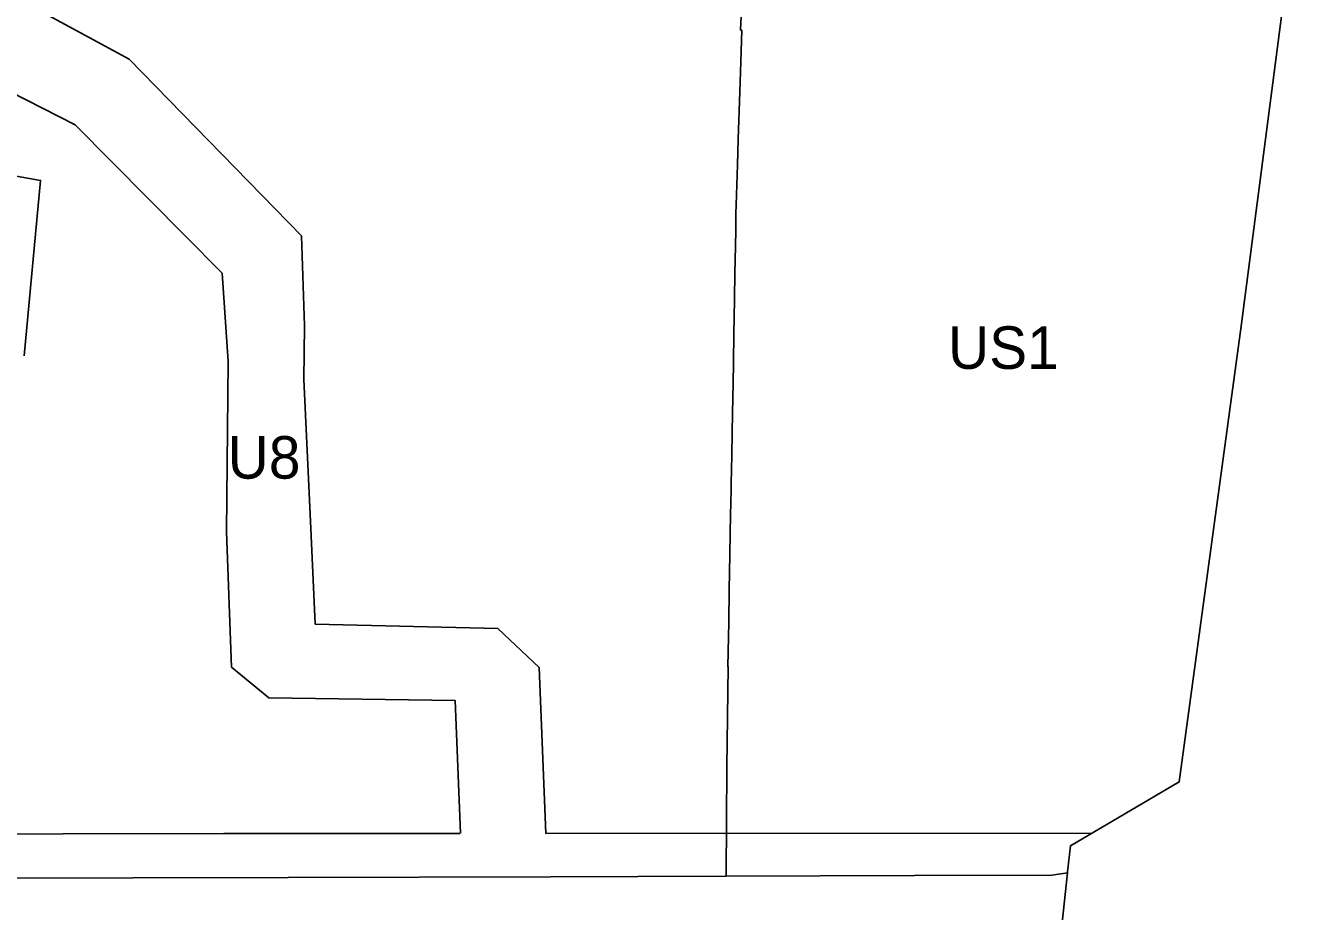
# Model space of a CAD drawing. Extents: x 7425930 to 7427318, y 5544765 to 5546387.
# Drawn here: x 7426835.8 to 7427135.3, y 5545452.3 to 5545660.7 of the extents above; entities that cross this region are included whole.
import ezdxf

# ---------------------------------------------------------------- set-up
doc = ezdxf.new("R2010")
doc.units = 0
for name, color, linetype in [('linie_rozgraniczajace', 7, 'Continuous'), ('linie_zabudowy_nieprzekraczalne', 7, 'Continuous'), ('linie_zabudowy_obowiazujace', 7, 'Continuous'), ('oznaczenia_przeznaczen', 7, 'Continuous')]:
    doc.layers.add(name, color=color, linetype=linetype)

msp = doc.modelspace()

# ---------------------------------------------------------------- linework, layer by layer
at = {"layer": 'linie_rozgraniczajace'}
for points in [[(7427135.34, 5545695.48), (7427121.59, 5545589.97), (7427107.05, 5545482.82), (7427081.49, 5545467.8), (7427080.83, 5545461.67), (7427080.8, 5545461.42), (7427077.1, 5545460.85), (7427044.85, 5545460.77), (7427000.54, 5545460.64), (7427000.55, 5545460.91), (7427000.71, 5545486.29), (7427001.05, 5545509.9), (7427000.97, 5545509.9), (7427001.03, 5545513.41), (7427001.16, 5545520.39), (7427001.29, 5545527.94), (7427001.44, 5545536.31), (7427001.61, 5545545.75), (7427001.66, 5545548.27), (7427001.72, 5545551.54), (7427001.74, 5545552.99), (7427001.86, 5545559.53), (7427001.96, 5545564.95), (7427002.04, 5545569.45), (7427002.17, 5545576.69), (7427002.25, 5545581.21), (7427002.38, 5545588.48), (7427002.44, 5545591.85), (7427002.52, 5545596.48), (7427002.62, 5545602.38), (7427002.74, 5545608.76), (7427002.81, 5545612.64), (7427002.82, 5545616.43), (7427002.91, 5545618.52), (7427003.2, 5545627.89), (7427003.39, 5545633.9), (7427003.75, 5545645.06), (7427003.98, 5545652.14), (7427004.21, 5545659.55), (7427003.95, 5545659.58), (7427003.96, 5545659.72), (7427004.14, 5545664.3)], [(7427004.14, 5545664.3), (7427003.96, 5545659.72), (7427003.95, 5545659.58), (7427004.21, 5545659.55), (7427003.98, 5545652.14), (7427003.75, 5545645.06), (7427003.39, 5545633.9), (7427003.2, 5545627.89), (7427002.91, 5545618.52), (7427002.82, 5545616.43), (7427002.81, 5545612.64), (7427002.74, 5545608.76), (7427002.62, 5545602.38), (7427002.52, 5545596.48), (7427002.44, 5545591.85), (7427002.38, 5545588.48), (7427002.25, 5545581.21), (7427002.17, 5545576.69), (7427002.04, 5545569.45), (7427001.96, 5545564.95), (7427001.86, 5545559.53), (7427001.74, 5545552.99), (7427001.72, 5545551.54), (7427001.66, 5545548.27), (7427001.61, 5545545.75), (7427001.44, 5545536.31), (7427001.29, 5545527.94), (7427001.16, 5545520.39), (7427001.03, 5545513.41), (7427000.97, 5545509.9), (7427001.05, 5545509.9), (7427000.71, 5545486.29), (7427000.55, 5545460.91), (7427000.54, 5545460.64), (7427000.42, 5545460.64), (7426959.25, 5545460.47), (7426897.61, 5545460.33), (7426824.49, 5545460.15)], [(7426835.5, 5545583.01), (7426839.39, 5545624.21), (7426830.19, 5545625.83)], [(7426830.19, 5545625.83), (7426839.39, 5545624.21), (7426835.5, 5545583.01)], [(7426824.49, 5545460.15), (7426897.61, 5545460.33), (7426959.25, 5545460.47), (7427000.42, 5545460.64), (7427000.54, 5545460.64), (7427044.85, 5545460.77), (7427077.1, 5545460.85), (7427080.8, 5545461.42), (7427075.49, 5545411.78)]]:
    msp.add_lwpolyline(points, dxfattribs=at)
at = {"layer": 'linie_zabudowy_nieprzekraczalne'}
for points in [[(7426876.75, 5545704.54), (7426867.16, 5545705.82), (7426852.17, 5545703.98), (7426841.25, 5545703.78), (7426837.32, 5545702.69), (7426811.3, 5545675.88), (7426838.51, 5545664.49), (7426860.23, 5545652.73), (7426900.71, 5545611.21), (7426901.45, 5545590.07), (7426901.26, 5545577.4), (7426902.91, 5545542.39), (7426903.95, 5545519.93), (7426946.89, 5545518.89), (7426956.59, 5545509.68), (7426958.18, 5545470.69)], [(7426938.12, 5545470.74), (7426936.85, 5545501.94), (7426893.04, 5545502.57), (7426884.3, 5545509.8), (7426883.08, 5545541.59), (7426883.51, 5545581.65), (7426882.07, 5545602.45), (7426847.55, 5545637.32), (7426832.14, 5545645.17), (7426796.12, 5545660.5)]]:
    msp.add_lwpolyline(points, dxfattribs=at)
at = {"layer": 'linie_zabudowy_obowiazujace'}
for points in [[(7426750.75, 5545472.83), (7426769.13, 5545470.46), (7426882.45, 5545470.69), (7426938.05, 5545470.71)], [(7426958.18, 5545470.69), (7427086.48, 5545470.73)]]:
    msp.add_lwpolyline(points, dxfattribs=at)

# ---------------------------------------------------------------- texts
at = {"layer": 'oznaczenia_przeznaczen'}
for s, p in [('US1', (7427052.73, 5545579.92)), ('U8', (7426883.39, 5545554.11))]:
    msp.add_text(s, height=10, dxfattribs=at).set_placement(p)

doc.saveas('drawing.dxf')
